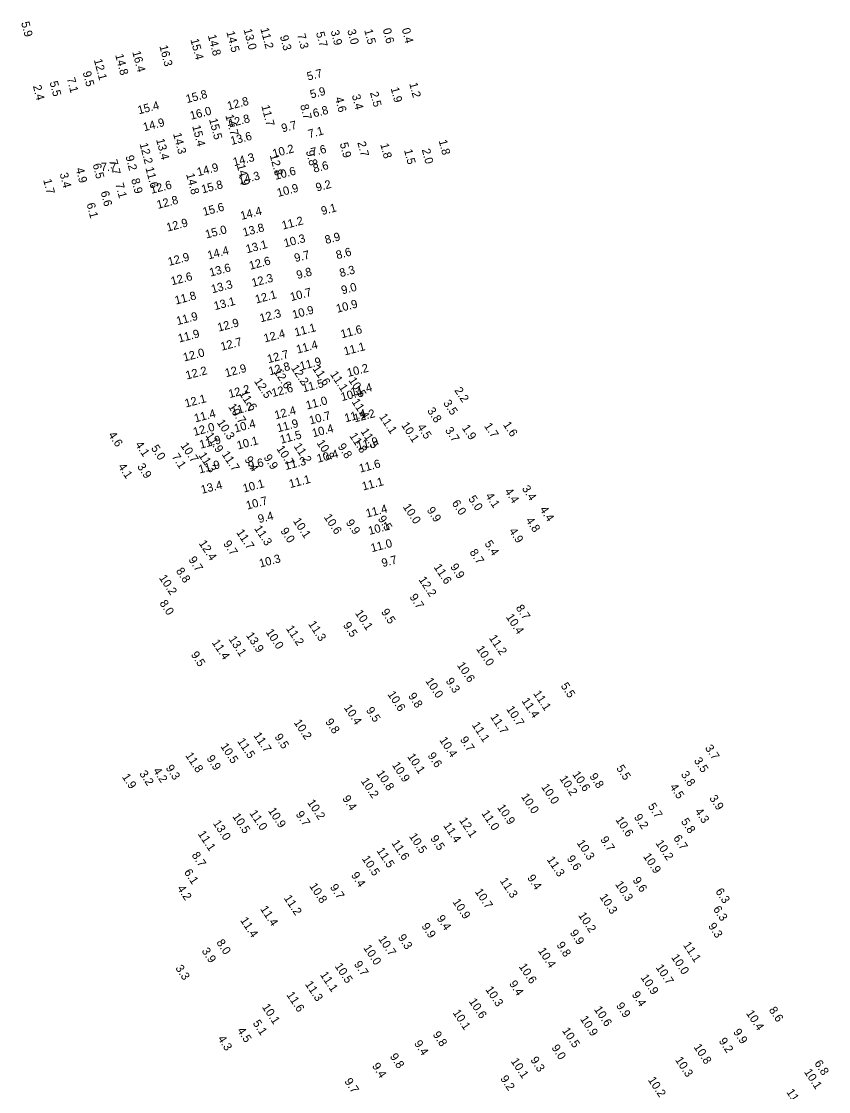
# Model space of a CAD drawing. Extents: x 815385 to 820851, y 582449 to 604245.
# Drawn here: x 816629 to 817112, y 597003 to 597644 of the extents above; entities that cross this region are included whole.
import ezdxf

# ---------------------------------------------------------------- set-up
doc = ezdxf.new("R2010")
doc.units = 0
for name, color, linetype in [('V-TOPO-SOUN-020509C', 7, 'Continuous'), ('V-TOPO-SOUN-021909', 7, 'Continuous'), ('V-TOPO-SOUN-EXCSS', 7, 'Continuous')]:
    doc.layers.add(name, color=color, linetype=linetype)

msp = doc.modelspace()

# ---------------------------------------------------------------- texts
at = {"layer": 'V-TOPO-SOUN-020509C'}
for s, p in [('2.2', (816887.81, 597422.92)), ('3.5', (816881.13, 597415.3)), ('3.8', (816871.5, 597410.73)), ('11.1 ', (816842.75, 597407.12)), ('10.1 ', (816856.02, 597402.01)), ('1.6', (816916.94, 597402.34)), ('11.8 ', (816824.95, 597395.63)), ('11.5 ', (816831.72, 597398.31)), ('4.5', (816865.52, 597400.95)), ('3.7', (816882.22, 597399.03)), ('1.9', (816892.31, 597400.41)), ('1.7', (816905.59, 597401.56)), ('4.6', (816680.61, 597396.26)), ('4.1', (816696.73, 597390.44)), ('11.2 ', (816791.63, 597389.45)), ('10.8 ', (816805.32, 597391.45)), ('9.8', (816817.96, 597389.24)), ('5.0', (816706.22, 597388.31)), ('7.1', (816718.56, 597383.19)), ('11.3 ', (816734.62, 597383.95)), ('11.7 ', (816748.52, 597384.63)), ('9.9', (816773.61, 597382.65)), ('10.7 ', (816781.33, 597387.92)), ('4.1', (816686.49, 597377.27)), ('3.9', (816697.92, 597377.28)), ('9.4', (816762.13, 597381.46)), ('3.4', (816928.24, 597364.1)), ('5.0', (816896.13, 597357.99)), ('4.1', (816906.39, 597359.7)), ('4.4', (816917.87, 597362.47)), ('10.0 ', (816857, 597353.17)), ('9.9', (816871.27, 597351.19)), ('6.0', (816886.3, 597355.36)), ('10.1 ', (816791.19, 597344.66)), ('10.6 ', (816809.68, 597346.98)), ('9.5', (816841.99, 597345.98)), ('4.4', (816938.86, 597351.58)), ('11.3 ', (816767.98, 597340.16)), ('9.0', (816783.66, 597338.71)), ('9.9', (816822.82, 597343.73)), ('4.8', (816930.53, 597345.07)), ('11.7 ', (816757.28, 597337.82)), ('5.4', (816905.83, 597331.09)), ('4.9', (816920.46, 597338.65)), ('12.4 ', (816734.82, 597331.27)), ('9.7', (816749.43, 597331.1)), ('8.7', (816896.89, 597325.94)), ('9.7', (816728.62, 597321.5)), ('8.8', (816721.15, 597314.78)), ('9.9', (816885.3, 597317.26)), ('10.2 ', (816711.02, 597310.58)), ('12.2 ', (816866.36, 597309.5)), ('8.0', (816711.3, 597295.44)), ('9.7', (816860.93, 597299.13)), ('10.1 ', (816828.33, 597289.5)), ('9.5', (816843.92, 597290.2)), ('10.4 ', (816918.68, 597287.14)), ('8.7', (816924.54, 597292.6)), ('11.2 ', (816787.05, 597280.24)), ('11.3 ', (816800.32, 597282.92)), ('9.5', (816821.15, 597282.24)), ('13.1 ', (816752.64, 597273.92)), ('13.9 ', (816763.08, 597276.13)), ('10.0 ', (816774.88, 597278.15)), ('11.2 ', (816908.53, 597274.61)), ('11.4 ', (816742.64, 597271.85)), ('10.0 ', (816900.88, 597268.07)), ('9.5', (816730.06, 597264.63)), ('10.6 ', (816889.36, 597258.29)), ('10.0 ', (816870.45, 597248.84)), ('9.3', (816882.61, 597248.81)), ('5.5', (816951.47, 597245.92)), ('10.6 ', (816847.79, 597240.9)), ('9.8', (816860.13, 597239.84)), ('11.4 ', (816928.03, 597236.9)), ('11.1 ', (816935.01, 597241.31)), ('10.4 ', (816821.66, 597232.85)), ('9.5', (816834.92, 597231.34)), ('10.7 ', (816918.9, 597231.98)), ('10.2 ', (816791.71, 597223.92)), ('9.8', (816810.51, 597224.42)), ('11.7 ', (816909.28, 597227.3)), ('11.7 ', (816767.54, 597216.21)), ('11.1 ', (816898.28, 597222.46)), ('11.5 ', (816757.86, 597212.72)), ('9.5', (816780.13, 597215.36)), ('10.4 ', (816878.82, 597213.42)), ('9.7', (816891.17, 597213.67)), ('11.8 ', (816726.76, 597204.21)), ('10.5 ', (816747.77, 597209.68)), ('10.1 ', (816859.61, 597203.56)), ('9.6', (816871.79, 597204.13)), ('3.7', (817037.82, 597208.71)), ('9.3', (816715.01, 597196.73)), ('9.9', (816739.44, 597202.47)), ('10.9 ', (816850.48, 597198.48)), ('5.5', (816984.72, 597196.59)), ('3.5', (817031.19, 597201.15)), ('1.9', (816688.83, 597191.4)), ('3.2', (816699.21, 597193.29)), ('4.2', (816707.43, 597195.03)), ('10.8 ', (816841.06, 597193.45)), ('10.6 ', (816958.42, 597192.91)), ('9.8', (816968.64, 597191.7)), ('3.8', (817023.38, 597192.89)), ('10.2 ', (816831.81, 597188.89)), ('10.0 ', (816939.79, 597185.32)), ('10.2 ', (816950.72, 597190.34)), ('4.5', (817016.72, 597185.39)), ('9.4', (816820.72, 597178.43)), ('10.0 ', (816927.73, 597179.59)), ('3.9', (817040.4, 597178.63)), ('10.2 ', (816799.75, 597175.98)), ('10.9 ', (816913.46, 597173.07)), ('5.7', (817003.65, 597173.75)), ('10.5 ', (816754.93, 597167.72)), ('11.0 ', (816765.16, 597169.61)), ('10.9 ', (816776.29, 597171.11)), ('9.7', (816792.84, 597168.99)), ('12.1 ', (816890.68, 597165.3)), ('11.0 ', (816904.01, 597169.56)), ('10.6 ', (816984.25, 597165.76)), ('9.2', (816995.33, 597167.28)), ('5.8', (817023.42, 597164.68)), ('4.3', (817031.72, 597170.79)), ('13.0 ', (816743.25, 597163.62)), ('11.4 ', (816881.17, 597162.19)), ('11.1 ', (816734.24, 597157.24)), ('10.5 ', (816860.67, 597155.8)), ('9.5', (816873.41, 597154.54)), ('9.7', (816975.13, 597153.86)), ('6.7', (817018.84, 597154.73)), ('11.5 ', (816841.27, 597147.15)), ('11.6 ', (816850.17, 597151.72)), ('10.3 ', (816961.06, 597151.83)), ('10.2 ', (817008.21, 597151.71)), ('8.7', (816730.52, 597144.51)), ('10.5 ', (816832.47, 597142.35)), ('11.3 ', (816943.14, 597141.88)), ('9.6', (816955.09, 597142.46)), ('10.9 ', (817000.79, 597143.8)), ('6.1', (816725.97, 597134.28)), ('9.4', (816825.96, 597132.52)), ('11.3 ', (816915.01, 597129.13)), ('9.4', (816931.37, 597130.91)), ('10.3 ', (816984.06, 597127.11)), ('9.6', (816994.51, 597129.51)), ('4.2', (816721.84, 597124.6)), ('10.8 ', (816800.97, 597125.95)), ('9.7', (816813.31, 597125.3)), ('10.7 ', (816900.06, 597122.64)), ('6.3', (817044.08, 597122.78)), ('11.2 ', (816785.73, 597118.78)), ('10.9 ', (816886.7, 597116.52)), ('10.3 ', (816974.69, 597119.47)), ('11.4 ', (816771.57, 597112.28)), ('10.2 ', (816961.97, 597108.42)), ('6.3', (817042.68, 597112.18)), ('11.4 ', (816759.6, 597105.48)), ('9.9', (816868.1, 597101.96)), ('9.4', (816877.22, 597106.66)), ('9.3', (817039.69, 597102.05)), ('10.7 ', (816842.23, 597094.34)), ('9.3', (816853.98, 597095.21)), ('9.9', (816956.91, 597097.99)), ('8.0', (816745.35, 597092.16)), ('10.0 ', (816833.33, 597088.95)), ('9.8', (816948.95, 597090.7)), ('11.1 ', (817024.7, 597090.68)), ('3.9', (816736.53, 597087.14)), ('10.4 ', (816937.86, 597087.23)), ('10.0 ', (817017.59, 597083.31)), ('3.3', (816720.79, 597076.83)), ('10.5 ', (816816.19, 597078.04)), ('9.7', (816827.7, 597079.22)), ('10.6 ', (816926.4, 597077.78)), ('10.7 ', (817008.34, 597077.23)), ('11.1 ', (816807.42, 597072.87)), ('10.9 ', (816999.33, 597071.23)), ('11.3 ', (816798.4, 597067.2)), ('10.3 ', (816906.35, 597064.08)), ('9.4', (816920.55, 597067.48)), ('11.6 ', (816787.3, 597060.83)), ('10.6 ', (816896.45, 597056.89)), ('9.4', (816993.98, 597060.97)), ('10.1 ', (816772.67, 597053.55)), ('10.1 ', (816886.81, 597050.14)), ('10.6 ', (816971.4, 597052.16)), ('9.9', (816984.6, 597054.32)), ('10.4 ', (817062.43, 597049.79)), ('8.6', (817076.03, 597051.77)), ('5.1', (816767.1, 597043.84)), ('10.9 ', (816963.06, 597046.35)), ('4.5', (816757.74, 597039.47)), ('9.8', (816874.84, 597037.06)), ('10.5 ', (816952.27, 597039.41)), ('9.9', (817054.7, 597038.61)), ('4.3', (816746.12, 597034.52)), ('9.4', (816863.7, 597031.71)), ('9.2', (817046.08, 597033.18)), ('9.8', (816849.16, 597023.89)), ('9.0', (816945.93, 597029.13)), ('10.8 ', (817031.04, 597029.58)), ('9.4', (816838.52, 597018.2)), ('10.1 ', (816921.61, 597021.06)), ('9.3', (816933.32, 597021.86)), ('10.3 ', (817019.94, 597021.85)), ('6.8', (817103.29, 597019.81)), ('10.1 ', (817097.14, 597014.63)), ('9.7', (816821.96, 597009.02)), ('9.2', (816915.28, 597010.67)), ('10.2 ', (817003.68, 597009.85)), ('11.1 ', (817086.53, 597002.57))]:
    msp.add_text(s, height=5, rotation=303.614, dxfattribs=at).set_placement(p)
at = {"layer": 'V-TOPO-SOUN-021909'}
for s, rotation, p in [('5.9', 284.724, (816628.61, 597643.19)), ('14.8 ', 284.724, (816740.39, 597635.45)), ('14.5 ', 284.724, (816751.48, 597637.54)), ('13.0 ', 284.724, (816761.77, 597639.03)), ('11.2 ', 284.724, (816771.84, 597639.6)), ('9.3', 284.724, (816783.52, 597635.01)), ('7.3', 284.724, (816793.78, 597635.98)), ('5.7', 284.724, (816805.15, 597637.09)), ('3.9', 284.724, (816813.9, 597638.12)), ('3.0', 284.724, (816823.85, 597638.61)), ('1.5', 284.724, (816834.03, 597638.69)), ('0.6', 284.724, (816845.08, 597639.21)), ('0.4', 284.724, (816856.47, 597639.35)), ('16.3 ', 284.724, (816711.38, 597629.1)), ('15.4 ', 284.724, (816729.97, 597633.05)), ('14.8 ', 284.724, (816684.93, 597623.82)), ('16.4 ', 284.724, (816695.15, 597625.66)), ('12.1 ', 284.724, (816672.17, 597620.87)), ('5.7', 14.724, (816800.45, 597608.43)), ('7.1', 284.724, (816655.97, 597609.71)), ('9.5', 284.724, (816665.47, 597613.46)), ('2.4', 284.724, (816635.69, 597605.18)), ('5.5', 284.724, (816645.66, 597607.52)), ('15.8 ', 14.724, (816727.96, 597594.95)), ('5.9', 14.724, (816802.3, 597597.7)), ('1.9', 284.724, (816849.83, 597603.91)), ('1.2', 284.724, (816860.95, 597606.73)), ('15.4 ', 14.724, (816699.13, 597588.22)), ('12.8 ', 14.724, (816752.74, 597590.77)), ('4.6', 284.724, (816816.48, 597598.04)), ('3.4', 284.724, (816826.59, 597599.61)), ('2.5', 284.724, (816837.45, 597601.23)), ('16.0 ', 14.724, (816730.41, 597584.96)), ('11.7 ', 284.724, (816772.42, 597593.23)), ('6.8', 14.724, (816803.98, 597586.37)), ('14.9 ', 14.724, (816702.34, 597578.06)), ('15.5 ', 284.724, (816741.12, 597585.28)), ('12.8 ', 14.724, (816753.42, 597580.33)), ('9.7', 14.724, (816785.13, 597577.41)), ('14.3 ', 284.724, (816719.6, 597576.58)), ('15.4 ', 284.724, (816731.03, 597581.16)), ('13.6 ', 14.724, (816754.63, 597569.83)), ('7.1', 14.724, (816801.12, 597573.96)), ('12.2 ', 284.724, (816699.53, 597570.58)), ('13.4 ', 284.724, (816709.43, 597573.15)), ('5.9', 284.724, (816819.35, 597570.76)), ('2.7', 284.724, (816829.89, 597571.41)), ('1.8', 284.724, (816843.62, 597570.32)), ('1.8', 284.724, (816878.59, 597572.45)), ('14.3 ', 14.724, (816756.18, 597557.13)), ('10.2 ', 14.724, (816779.86, 597562.29)), ('7.6', 14.724, (816802.77, 597562.97)), ('1.5', 284.724, (816857.83, 597566.81)), ('2.0', 284.724, (816868.48, 597567.09)), ('6.5', 284.724, (816671.42, 597558.22)), ('7.7', 284.724, (816681.2, 597560.56)), ('9.2', 284.724, (816691.07, 597563.08)), ('14.9 ', 14.724, (816734.63, 597551.16)), ('8.6', 14.724, (816804.11, 597553.25)), ('3.4', 284.724, (816651.7, 597552.7)), ('4.9', 284.724, (816661.27, 597555.69)), ('14.8 ', 284.724, (816727.4, 597552.37)), ('14.3 ', 14.724, (816759.43, 597546.11)), ('10.6 ', 14.724, (816780.95, 597548.96)), ('1.7', 284.724, (816641.84, 597548.94)), ('7.1', 284.724, (816684.99, 597546.54)), ('8.9', 284.724, (816694.49, 597549.28)), ('12.6 ', 14.724, (816706.69, 597540.62)), ('15.8 ', 14.724, (816737.25, 597540.83)), ('10.9 ', 14.724, (816782.5, 597538.75)), ('9.2', 14.724, (816805.7, 597541.95)), ('6.6', 284.724, (816676.21, 597541.68)), ('12.8 ', 14.724, (816710.54, 597531.58)), ('6.1', 284.724, (816667.81, 597534.59)), ('15.6 ', 14.724, (816738.05, 597527.38)), ('14.4 ', 14.724, (816760.6, 597524.97)), ('9.1', 14.724, (816808.89, 597527.87)), ('12.9 ', 14.724, (816716.31, 597517.97)), ('11.2 ', 14.724, (816785.4, 597519.17)), ('15.0 ', 14.724, (816739.59, 597513.83)), ('13.8 ', 14.724, (816762.02, 597515.01)), ('13.1 ', 14.724, (816763.89, 597505.01)), ('10.3 ', 14.724, (816786.62, 597508.55)), ('8.9', 14.724, (816811.15, 597510.53)), ('14.4 ', 14.724, (816740.87, 597501.31)), ('9.7', 14.724, (816792.87, 597499.68)), ('8.6', 14.724, (816817.83, 597501.43)), ('12.9 ', 14.724, (816717.22, 597497.45)), ('12.6 ', 14.724, (816765.81, 597495.13)), ('12.6 ', 14.724, (816718.99, 597485.79)), ('13.6 ', 14.724, (816742.02, 597491.01)), ('9.8', 14.724, (816794.13, 597489.51)), ('8.3', 14.724, (816819.93, 597490.69)), ('13.3 ', 14.724, (816743.13, 597481.02)), ('12.3 ', 14.724, (816767.34, 597484.82)), ('9.0', 14.724, (816820.99, 597480.38)), ('11.8 ', 14.724, (816721.31, 597474.28)), ('12.1 ', 14.724, (816769.44, 597474.9)), ('10.7 ', 14.724, (816790.39, 597476.35)), ('13.1 ', 14.724, (816744.72, 597470.94)), ('10.9 ', 14.724, (816817.92, 597469.34)), ('11.9 ', 14.724, (816722.27, 597461.96)), ('12.3 ', 14.724, (816772.13, 597463.64)), ('10.9 ', 14.724, (816791.67, 597465.74)), ('12.9 ', 14.724, (816746.86, 597458.05)), ('11.1 ', 14.724, (816792.94, 597455.13)), ('11.6 ', 14.724, (816820.64, 597454.07)), ('11.9 ', 14.724, (816723.27, 597451.51)), ('12.4 ', 14.724, (816774.57, 597451.57)), ('12.7 ', 14.724, (816748.75, 597446.63)), ('11.4 ', 14.724, (816794.08, 597444.91)), ('11.1 ', 14.724, (816822.44, 597443.8)), ('12.0 ', 14.724, (816726.29, 597440.15)), ('12.7 ', 14.724, (816776.69, 597439.13)), ('11.9 ', 14.724, (816796.14, 597434.89)), ('12.2 ', 14.724, (816727.84, 597429.38)), ('12.9 ', 14.724, (816751.38, 597430.78)), ('12.8 ', 14.724, (816777.52, 597431.89)), ('10.2 ', 14.724, (816824.43, 597430.91)), ('11.5 ', 14.724, (816797.65, 597421.71)), ('12.2 ', 14.724, (816753.46, 597418.26)), ('12.6 ', 14.724, (816779.3, 597418.88)), ('10.4 ', 14.724, (816820.73, 597416.44)), ('12.1 ', 14.724, (816727.27, 597412.62)), ('11.0 ', 14.724, (816799.82, 597411.41)), ('11.4 ', 14.724, (816732.95, 597403.7)), ('11.2 ', 14.724, (816755.17, 597407.94)), ('12.4 ', 14.724, (816781.03, 597405.51)), ('10.7 ', 14.724, (816801.8, 597402.44)), ('11.4 ', 14.724, (816822.93, 597403.76)), ('10.4 ', 14.724, (816756.88, 597397.63)), ('11.9 ', 14.724, (816782.46, 597397.77)), ('12.0 ', 14.724, (816732.34, 597395.56)), ('11.5 ', 14.724, (816784.35, 597390.92)), ('10.4 ', 14.724, (816803.54, 597394.77)), ('11.9 ', 14.724, (816736.06, 597387.93)), ('10.1 ', 14.724, (816758.47, 597387.43))]:
    msp.add_text(s, height=5, rotation=rotation, dxfattribs=at).set_placement(p)
at = {"layer": 'V-TOPO-SOUN-EXCSS'}
for s, rotation, p in [('8.7', 284.724, (816795.65, 597593.65)), ('14.7 ', 284.724, (816750.86, 597587.6)), ('12.8 ', 284.724, (816777.47, 597563.66)), ('9.8', 284.724, (816799.08, 597566.12)), ('14.9 ', 284.724, (816757.71, 597557.77)), ('11.6 ', 284.724, (816703.04, 597556.09)), ('12.6 ', 303.614, (816779.64, 597434.15)), ('12.2 ', 303.614, (816789.96, 597436.34)), ('11.6 ', 303.614, (816802.88, 597436.01)), ('12.5 ', 303.614, (816767.9, 597428.38)), ('11.1 ', 303.614, (816813.39, 597432.54)), ('10.5 ', 303.614, (816824.43, 597428.88)), ('11.4 ', 14.724, (816826.64, 597419.34)), ('11.6 ', 303.614, (816758.98, 597420.94)), ('11.4 ', 303.614, (816826.31, 597416.04)), ('10.7 ', 303.614, (816752.36, 597413.11)), ('12.2 ', 14.724, (816828.4, 597403.7)), ('10.3 ', 303.614, (816745.64, 597403.59)), ('11.9 ', 303.614, (816738.87, 597395.86)), ('10.7 ', 303.614, (816723.87, 597389.87)), ('11.9 ', 14.724, (816830.28, 597387.05)), ('10.4 ', 14.724, (816806.38, 597379.54)), ('11.9 ', 14.724, (816735.54, 597373.09)), ('9.6', 14.724, (816765.26, 597375.24)), ('11.3 ', 14.724, (816787.06, 597375.14)), ('11.6 ', 14.724, (816831.62, 597373.59)), ('11.1 ', 14.724, (816789.71, 597364.34)), ('13.4 ', 14.724, (816736.97, 597360.91)), ('10.1 ', 14.724, (816762.07, 597361.67)), ('11.1 ', 14.724, (816833.42, 597362.89)), ('10.7 ', 14.724, (816764, 597351.43)), ('11.4 ', 14.724, (816835.71, 597346.67)), ('9.4', 14.724, (816771.14, 597343.33)), ('10.1 ', 14.724, (816837.17, 597336.3)), ('11.0 ', 14.724, (816838.63, 597325.94)), ('10.3 ', 14.724, (816771.85, 597316.74)), ('9.7', 14.724, (816845.14, 597317)), ('11.6 ', 303.614, (816875.45, 597317.08))]:
    msp.add_text(s, height=5, rotation=rotation, dxfattribs=at).set_placement(p)
msp.add_text('7.7', height=5, dxfattribs=at).set_placement((816676.38, 597554.31))

doc.saveas('drawing.dxf')
